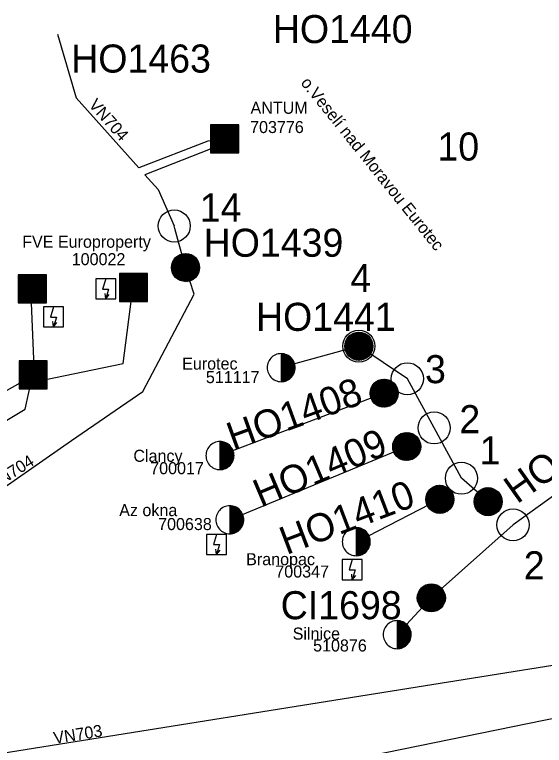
# Model space of a CAD drawing. Extents: x -546092 to -542700, y -1196659 to -1193917.
# Drawn here: x -544579 to -543918, y -1194828 to -1193917 of the extents above; entities that cross this region are included whole.
import ezdxf

# ---------------------------------------------------------------- set-up
doc = ezdxf.new("R2010")
doc.units = 0
for name, color, linetype in [('Default', 7, 'Continuous'), ('Vrstva 1', 7, 'Continuous'), ('Vrstva 2', 7, 'Continuous'), ('Vrstva 3', 7, 'Continuous'), ('Vrstva 4', 7, 'Continuous'), ('Vrstva 47', 7, 'Continuous'), ('Vrstva 5', 7, 'Continuous')]:
    doc.layers.add(name, color=color, linetype=linetype)

# ---------------------------------------------------------------- blocks, each defined once
blk = doc.blocks.new('PS700')
at = {"layer": 'Vrstva 47'}
for points in [[(12.48, 12.51), (-12.52, 12.51)], [(-12.52, 12.51), (-12.52, -12.49)], [(-0.02, 12.51), (-3.96, -0.19)], [(12.48, -12.49), (12.48, 12.51)], [(-3.96, -0.19), (3.52, -0.19)], [(-0.02, -12.49), (-0.71, -5.7)], [(3.52, -0.19), (-0.02, -12.49)], [(-0.02, -12.49), (4.31, -7.08)], [(-12.52, -12.49), (12.48, -12.49)]]:
    blk.add_lwpolyline(points, dxfattribs=at)
blk = doc.blocks.new('PS140')
at = {"layer": 'Default'}
for p, q in [((-17.49, -0.01), (0.01, 17.49)), ((-17.43, -1.37), (1.37, 17.43)), ((-17.42, 1.47), (-1.47, 17.42)), ((-17.29, -2.63), (2.63, 17.29)), ((-17.21, 3.1), (-3.1, 17.21)), ((-17.06, -3.82), (3.82, 17.06)), ((-16.77, -4.95), (4.95, 16.77)), ((-16.77, 4.95), (-4.95, 16.77)), ((-16.42, -6.01), (6.01, 16.42)), ((-16.02, -7.02), (7.02, 16.02)), ((-15.93, 7.2), (-7.2, 15.93)), ((-15.56, -7.98), (7.98, 15.56)), ((-15.06, -8.89), (8.89, 15.06)), ((-14.51, -9.76), (9.76, 14.51)), ((-13.92, -10.58), (10.58, 13.92)), ((-13.75, 10.8), (-10.8, 13.75)), ((-13.29, -11.36), (11.36, 13.29)), ((-12.62, -12.11), (12.11, 12.62)), ((-11.91, -12.81), (12.81, 11.91)), ((-11.15, -13.47), (13.47, 11.15)), ((-10.36, -14.09), (14.09, 10.36)), ((-9.52, -14.67), (14.67, 9.52)), ((-8.64, -15.2), (15.2, 8.64)), ((-7.72, -15.69), (15.69, 7.72)), ((-6.74, -16.13), (16.13, 6.74)), ((-5.72, -16.52), (16.52, 5.72)), ((-4.64, -16.86), (16.86, 4.64)), ((-3.5, -17.13), (17.13, 3.5)), ((-2.29, -17.34), (17.34, 2.29)), ((-1, -17.46), (17.46, 1)), ((0.39, -17.48), (17.48, -0.39)), ((1.91, -17.38), (17.38, -1.91)), ((3.59, -17.11), (17.11, -3.59)), ((5.53, -16.59), (16.59, -5.53)), ((7.96, -15.57), (15.57, -7.96))]:
    blk.add_line(p, q, dxfattribs=at)
blk.add_circle((0, 0), 17.49, dxfattribs=at)
blk = doc.blocks.new('PS800')
at = {"layer": 'Vrstva 2'}
blk.add_circle((0, -0.01), 20, dxfattribs=at)
blk = doc.blocks.new('PS630')
at = {"layer": 'Default'}
for p, q in [((-16.61, -14.95), (17.07, 18.74)), ((-16.61, -13.53), (15.66, 18.74)), ((-16.61, -12.12), (14.24, 18.74)), ((-16.61, -10.71), (12.83, 18.74)), ((-16.61, -9.29), (11.41, 18.74)), ((-16.61, -7.88), (10, 18.74)), ((-16.61, -6.46), (8.59, 18.74)), ((-16.61, -5.05), (7.17, 18.74)), ((-16.61, -3.63), (5.76, 18.74)), ((-16.61, -2.22), (4.34, 18.74)), ((-16.61, -0.81), (2.93, 18.74)), ((-16.61, 0.61), (1.51, 18.74)), ((-16.61, 2.02), (0.1, 18.74)), ((-16.61, 3.44), (-1.31, 18.74)), ((-16.61, 4.85), (-2.73, 18.74)), ((-16.61, 6.27), (-4.14, 18.74)), ((-16.61, 7.68), (-5.56, 18.74)), ((-16.61, 9.09), (-6.97, 18.74)), ((-16.61, 10.51), (-8.38, 18.74)), ((-16.61, 11.92), (-9.8, 18.74)), ((-16.61, 13.34), (-11.21, 18.74)), ((-16.61, 14.75), (-12.63, 18.74)), ((-16.61, 16.16), (-14.04, 18.74)), ((-16.61, 17.58), (-15.46, 18.74)), ((-16.51, -16.26), (18.39, 18.64)), ((-15.1, -16.26), (18.39, 17.22)), ((-13.69, -16.26), (18.39, 15.81)), ((-12.27, -16.26), (18.39, 14.39)), ((-10.86, -16.26), (18.39, 12.98)), ((-9.44, -16.26), (18.39, 11.57)), ((-8.03, -16.26), (18.39, 10.15)), ((-6.62, -16.26), (18.39, 8.74)), ((-5.2, -16.26), (18.39, 7.32)), ((-3.79, -16.26), (18.39, 5.91)), ((-2.37, -16.26), (18.39, 4.5)), ((-0.96, -16.26), (18.39, 3.08)), ((0.46, -16.26), (18.39, 1.67)), ((1.87, -16.26), (18.39, 0.25)), ((3.28, -16.26), (18.39, -1.16)), ((4.7, -16.26), (18.39, -2.58)), ((6.11, -16.26), (18.39, -3.99)), ((7.53, -16.26), (18.39, -5.4)), ((8.94, -16.26), (18.39, -6.82)), ((10.36, -16.26), (18.39, -8.23)), ((11.77, -16.26), (18.39, -9.65)), ((13.18, -16.26), (18.39, -11.06)), ((14.6, -16.26), (18.39, -12.48)), ((16.01, -16.26), (18.39, -13.89)), ((17.43, -16.26), (18.39, -15.3))]:
    blk.add_line(p, q, dxfattribs=at)
for points in [[(-16.61, 18.74), (-16.61, -16.26)], [(18.39, 18.74), (-16.61, 18.74)], [(-16.61, 18.74), (-16.61, -16.26)], [(18.39, -16.26), (18.39, 18.74)], [(-16.61, -16.26), (18.39, -16.26)]]:
    blk.add_lwpolyline(points, dxfattribs=at)
blk = doc.blocks.new('PS611')
at = {"layer": 'Default'}
for p, q in [((0, 16.16), (1.27, 17.43)), ((0, 14.75), (2.54, 17.29)), ((0, 13.33), (3.75, 17.09)), ((0, 11.92), (4.86, 16.79)), ((0, 10.51), (5.93, 16.44)), ((0, 9.09), (6.95, 16.05)), ((0, 7.68), (7.9, 15.58)), ((0, 6.26), (8.83, 15.1)), ((0, 4.85), (9.69, 14.54)), ((0, 3.44), (10.52, 13.96)), ((0, 2.02), (11.3, 13.33)), ((0, 0.61), (12.05, 12.66)), ((0, -0.81), (12.76, 11.95)), ((0, -2.22), (13.42, 11.2)), ((0, -3.64), (14.05, 10.41)), ((0, -5.05), (14.62, 9.57)), ((0, -6.46), (15.17, 8.71)), ((0, -7.88), (15.65, 7.77)), ((0, -9.29), (16.1, 6.81)), ((0, -10.71), (16.49, 5.79)), ((0, -12.12), (16.83, 4.71)), ((0, -13.53), (17.12, 3.59)), ((0, -14.95), (17.32, 2.37)), ((0, -16.36), (17.44, 1.08)), ((0.29, -17.49), (17.48, -0.29)), ((1.78, -17.41), (17.4, -1.79)), ((3.46, -17.15), (17.14, -3.46)), ((5.36, -16.66), (16.65, -5.37)), ((7.78, -15.65), (15.64, -7.79))]:
    blk.add_line(p, q, dxfattribs=at)
for points in [[(17.5, 0), (17.4, 1.83), (17.12, 3.64), (16.64, 5.4), (15.98, 7.11), (15.15, 8.75), (14.15, 10.28), (13, 11.71), (11.71, 13), (10.28, 14.15), (8.75, 15.15), (7.11, 15.98), (5.4, 16.64), (3.64, 17.12), (1.83, 17.4), (0, 17.5), (-1.83, 17.4), (-3.64, 17.12), (-5.41, 16.64), (-7.12, 15.98), (-8.75, 15.15), (-10.29, 14.15), (-11.71, 13), (-13.01, 11.71), (-14.16, 10.28), (-15.16, 8.75), (-15.99, 7.11), (-16.65, 5.4), (-17.12, 3.64), (-17.41, 1.83), (-17.5, 0), (-17.41, -1.83), (-17.12, -3.64), (-16.65, -5.41), (-15.99, -7.12), (-15.16, -8.75), (-14.16, -10.29), (-13.01, -11.71), (-11.71, -13.01), (-10.29, -14.16), (-8.75, -15.16), (-7.12, -15.99), (-5.41, -16.65), (-3.64, -17.12), (-1.83, -17.41), (0, -17.5), (1.83, -17.41), (3.64, -17.12), (5.4, -16.65), (7.12, -15.99), (8.75, -15.16), (10.28, -14.16), (11.71, -13.01), (13, -11.71), (14.15, -10.29), (15.15, -8.75), (15.98, -7.12), (16.64, -5.41), (17.12, -3.64), (17.4, -1.83), (17.5, 0)], [(0, 17.5), (0, -17.5)]]:
    blk.add_lwpolyline(points, dxfattribs=at)
blk = doc.blocks.new('PS631')
at = {"layer": 'Default'}
for p, q in [((-16.61, -14.95), (17.07, 18.74)), ((-16.61, -13.53), (15.66, 18.74)), ((-16.61, -12.12), (14.24, 18.74)), ((-16.61, -10.71), (12.83, 18.74)), ((-16.61, -9.29), (11.41, 18.74)), ((-16.61, -7.88), (10, 18.74)), ((-16.61, -6.46), (8.59, 18.74)), ((-16.61, -5.05), (7.17, 18.74)), ((-16.61, -3.63), (5.76, 18.74)), ((-16.61, -2.22), (4.34, 18.74)), ((-16.61, -0.81), (2.93, 18.74)), ((-16.61, 0.61), (1.51, 18.74)), ((-16.61, 2.02), (0.1, 18.74)), ((-16.61, 3.44), (-1.31, 18.74)), ((-16.61, 4.85), (-2.73, 18.74)), ((-16.61, 6.27), (-4.14, 18.74)), ((-16.61, 7.68), (-5.56, 18.74)), ((-16.61, 9.09), (-6.97, 18.74)), ((-16.61, 10.51), (-8.38, 18.74)), ((-16.61, 11.92), (-9.8, 18.74)), ((-16.61, 13.34), (-11.21, 18.74)), ((-16.61, 14.75), (-12.63, 18.74)), ((-16.61, 16.16), (-14.04, 18.74)), ((-16.61, 17.58), (-15.46, 18.74)), ((-16.51, -16.26), (18.39, 18.64)), ((-15.1, -16.26), (18.39, 17.22)), ((-13.69, -16.26), (18.39, 15.81)), ((-12.27, -16.26), (18.39, 14.39)), ((-10.86, -16.26), (18.39, 12.98)), ((-9.44, -16.26), (18.39, 11.57)), ((-8.03, -16.26), (18.39, 10.15)), ((-6.62, -16.26), (18.39, 8.74)), ((-5.2, -16.26), (18.39, 7.32)), ((-3.79, -16.26), (18.39, 5.91)), ((-2.37, -16.26), (18.39, 4.5)), ((-0.96, -16.26), (18.39, 3.08)), ((0.46, -16.26), (18.39, 1.67)), ((1.87, -16.26), (18.39, 0.25)), ((3.28, -16.26), (18.39, -1.16)), ((4.7, -16.26), (18.39, -2.58)), ((6.11, -16.26), (18.39, -3.99)), ((7.53, -16.26), (18.39, -5.4)), ((8.94, -16.26), (18.39, -6.82)), ((10.36, -16.26), (18.39, -8.23)), ((11.77, -16.26), (18.39, -9.65)), ((13.18, -16.26), (18.39, -11.06)), ((14.6, -16.26), (18.39, -12.48)), ((16.01, -16.26), (18.39, -13.89)), ((17.43, -16.26), (18.39, -15.3))]:
    blk.add_line(p, q, dxfattribs=at)
for points in [[(-16.61, 18.74), (-16.61, -16.26)], [(18.39, 18.74), (-16.61, 18.74)], [(-16.61, 18.74), (-16.61, -16.26)], [(18.39, -16.26), (18.39, 18.74)], [(-16.61, -16.26), (18.39, -16.26)]]:
    blk.add_lwpolyline(points, dxfattribs=at)

msp = doc.modelspace()

# ---------------------------------------------------------------- linework, layer by layer
at = {"layer": 'Vrstva 1'}
for points in [[(-544525.65, -1193940.93), (-544502.34, -1194020.23)], [(-544502.34, -1194020.23), (-544424.51, -1194107.53)], [(-544318.13, -1194072.72), (-544338.42, -1194074.48), (-544424.51, -1194107.53)], [(-544318.13, -1194072.72), (-544335.39, -1194084.55), (-544416.73, -1194116.25)], [(-544416.73, -1194116.25), (-544400.4, -1194134.58)], [(-544400.4, -1194134.58), (-544380.12, -1194180.21)], [(-544366.07, -1194232.09), (-544366.07, -1194232.09), (-544379.32, -1194183.55), (-544380.12, -1194180.21)], [(-544925.5, -1194716.9), (-544893.06, -1194695.43), (-544611.95, -1194519.78), (-544508.51, -1194447.58), (-544419.53, -1194386.55), (-544355.13, -1194265.22), (-544366.07, -1194232.09)], [(-544542.3, -1194371.88), (-544443.78, -1194351.84), (-544431.85, -1194258.26)], [(-544554.83, -1194356.02), (-544558.81, -1194266.32)], [(-544149.87, -1194330.13), (-544245.01, -1194356.07)], [(-544089.34, -1194370.69), (-544149.87, -1194330.13)], [(-545148.86, -1194733.03), (-545097.22, -1194694.01), (-544858.8, -1194583.9), (-544566.1, -1194408.5), (-544557.1, -1194367.2)], [(-544868.4, -1194543.3), (-544557.1, -1194367.2)], [(-544055.95, -1194432.01), (-544089.34, -1194370.69)], [(-544118.35, -1194388.71), (-544321.67, -1194465.8), (-544323.1, -1194466.57)], [(-543771.73, -1194419.42), (-543957.54, -1194552.9)], [(-544021.92, -1194494.8), (-544055.95, -1194432.01)], [(-544309.14, -1194545.62), (-544090.16, -1194455.25)], [(-543988.63, -1194523.97), (-544021.92, -1194494.8)], [(-544048.94, -1194521.07), (-544151.3, -1194573.47)], [(-543957.54, -1194552.9), (-544059.47, -1194643.95)], [(-544059.47, -1194643.95), (-544100.62, -1194688.42), (-544101.94, -1194689.85)], [(-543754.51, -1194703.95), (-544879.02, -1194883.37)], [(-544664.83, -1194948.52), (-543682.87, -1194748.36)]]:
    msp.add_lwpolyline(points, dxfattribs=at)

# ---------------------------------------------------------------- block references
at = {"layer": 'Vrstva 2'}
for p, rotation in [((-544366.07, -1194232.09), -63.42660830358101), ((-544149.87, -1194330.13), -10.619555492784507), ((-544118.35, -1194388.71), 85.67093891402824), ((-544090.16, -1194455.25), 79.38501394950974), ((-544048.94, -1194521.07), -168.39902229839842), ((-543988.63, -1194523.97), 14.597394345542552), ((-544059.47, -1194643.95), 47.22069436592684)]:
    msp.add_blockref('PS140', p, dxfattribs=dict(at, rotation=rotation))
at = {"layer": 'Vrstva 3'}
for name, p in [('PS630', (-544318.13, -1194072.72)), ('PS631', (-544558.11, -1194259.67)), ('PS631', (-544431.85, -1194258.26)), ('PS630', (-544557.1, -1194367.2)), ('PS611', (-544323.1, -1194466.57)), ('PS611', (-544310.83, -1194546.53)), ('PS611', (-544153.06, -1194573.87))]:
    msp.add_blockref(name, p, dxfattribs=at)
for p, rotation in [((-544246.76, -1194356.89), -0.21670834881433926), ((-544101.94, -1194689.85), -0.25350275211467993)]:
    msp.add_blockref('PS611', p, dxfattribs=dict(at, rotation=rotation))
at = {"layer": 'Vrstva 4'}
for p in [(-544465.53, -1194258.64), (-544530.76, -1194293.56), (-544327.37, -1194577.39), (-544158.08, -1194608.77)]:
    msp.add_blockref('PS700', p, dxfattribs=at)
at = {"layer": 'Vrstva 5'}
for p, rotation in [((-544380.12, -1194180.21), 116.01359716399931), ((-544149.87, -1194330.13), 118.30990280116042), ((-544089.34, -1194370.69), -61.68772496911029), ((-544055.95, -1194432.01), -61.42961386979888), ((-544021.92, -1194494.8), -61.54271109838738), ((-543957.54, -1194552.9), 56.44339170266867)]:
    msp.add_blockref('PS800', p, dxfattribs=dict(at, rotation=rotation))

# ---------------------------------------------------------------- texts
at = {"layer": 'Vrstva 1'}
for s, rotation, p in [('o.Veselí nad Moravou Eurotec', 308.789, (-544223.17, -1194002.09)), ('VN704', 311.715, (-544487.78, -1194029.87)), ('VN704', 31.999, (-544605.47, -1194509.9)), ('VN703', 9.065, (-544529.54, -1194826.18))]:
    msp.add_text(s, height=15, rotation=rotation, dxfattribs=at).set_placement(p)
at = {"layer": 'Vrstva 2'}
for s, p in [('HO1440', (-544257.21, -1193952.17)), ('HO1463', (-544508.74, -1193988.92)), ('HO1439', (-544343.53, -1194218.62)), ('HO1441', (-544278.21, -1194310.99)), ('CI1698', (-544247.37, -1194670.59))]:
    msp.add_text(s, height=35, dxfattribs=at).set_placement(p)
for s, rotation, p in [('HO1408', 19.97, (-544306.56, -1194460.62)), ('HO1412', 35.383, (-543952.52, -1194527.51)), ('HO1409', 22.934, (-544272.1, -1194531.73)), ('HO1410', 20.797, (-544240.21, -1194590.7))]:
    msp.add_text(s, height=35, rotation=rotation, dxfattribs=at).set_placement(p)
at = {"layer": 'Vrstva 3'}
for s, p in [('ANTUM', (-544285.04, -1194040.31)), ('703776', (-544285.53, -1194064.32)), ('FVE Europroperty', (-544569.85, -1194207.33)), ('100022', (-544508.07, -1194229.08)), ('Eurotec', (-544370.31, -1194359.31)), ('511117', (-544340.67, -1194376.16)), ('Clancy', (-544431.14, -1194474.32)), ('700017', (-544410.15, -1194489.72)), ('Az okna', (-544448.83, -1194542.06)), ('700638', (-544400.27, -1194559.41)), ('Branopac', (-544290.45, -1194603.21)), ('700347', (-544254.07, -1194618.61)), ('Silnice', (-544232.41, -1194695.98)), ('510876', (-544206.93, -1194710.82))]:
    msp.add_text(s, height=15, dxfattribs=at).set_placement(p)
at = {"layer": 'Vrstva 5'}
for s, p in [('10', (-544051.87, -1194098.62)), ('14', (-544348.3, -1194174.7)), ('4', (-544160.47, -1194262.71)), ('3', (-544067.32, -1194376.25)), ('2', (-544024.47, -1194438.62)), ('1', (-543999.21, -1194477.49)), ('2', (-543944.11, -1194620.85))]:
    msp.add_text(s, height=35, dxfattribs=at).set_placement(p)

doc.saveas('drawing.dxf')
